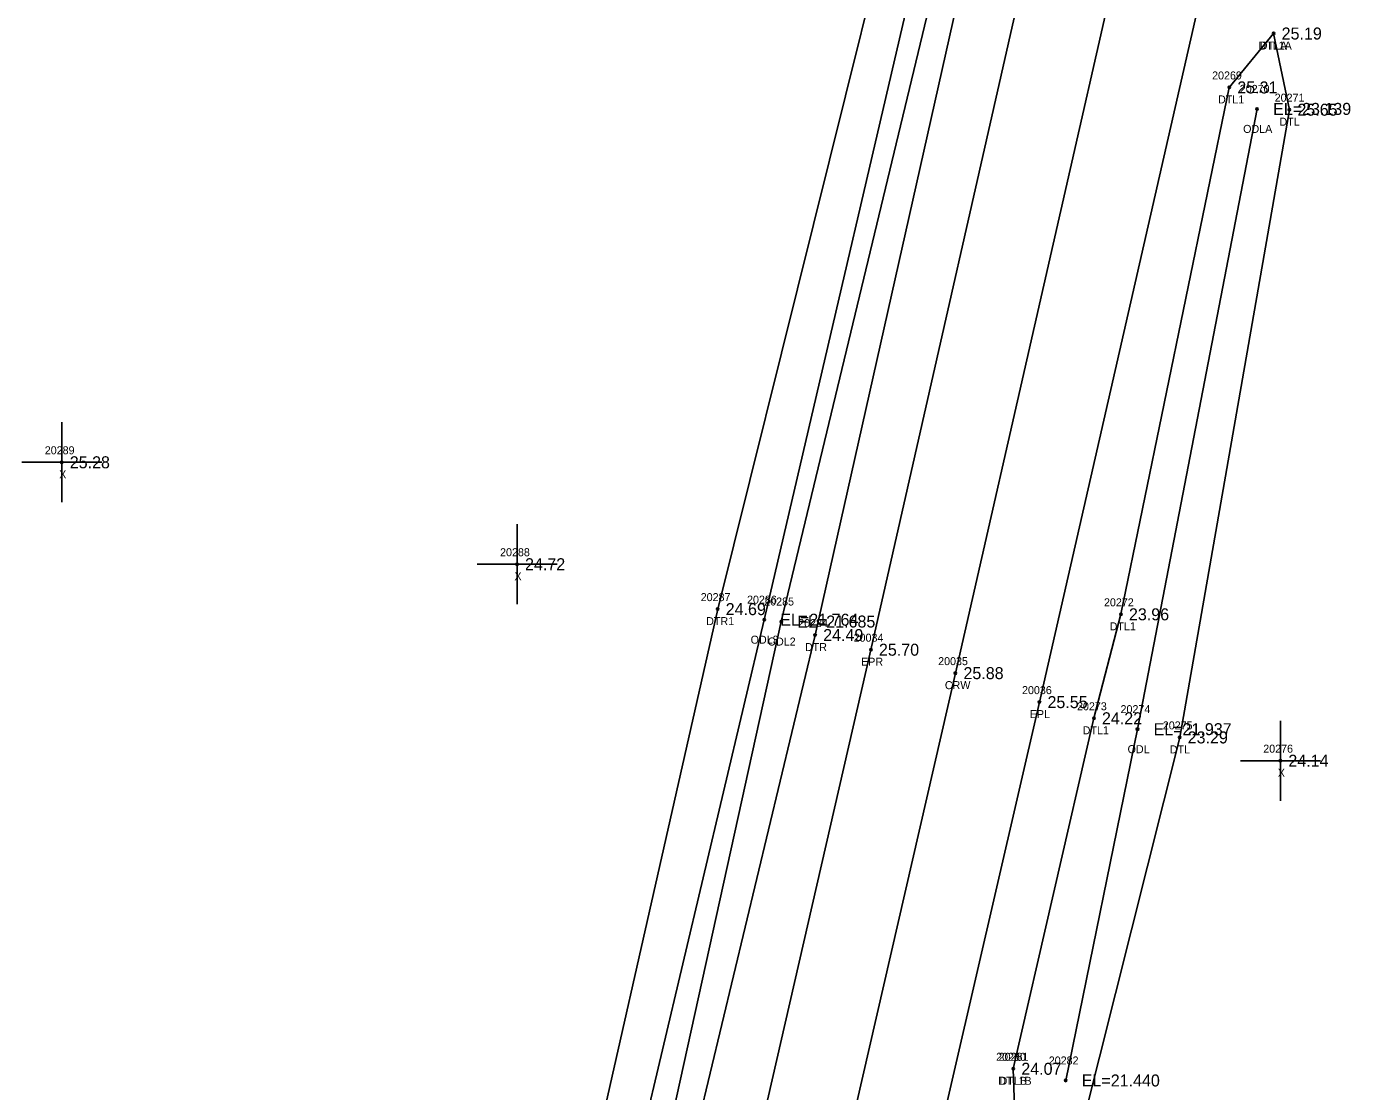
# Model space of a CAD drawing. Extents: x 2655177 to 2656219, y 761780 to 764748.
# Drawn here: x 2655847.5 to 2656013, y 764278.4 to 764411.4 of the extents above; entities that cross this region are included whole.
import ezdxf

# ---------------------------------------------------------------- set-up
doc = ezdxf.new("R2010")
doc.units = 0
for name, color, linetype in [('RD_DTM_BkLn1', 7, 'Continuous'), ('RD_EX_H2O', 7, 'Continuous'), ('RD_EX_H2O_txCode', 7, 'Continuous'), ('RD_EX_Misc', 7, 'Continuous'), ('RD_EX_Misc_txCode', 7, 'Continuous'), ('RD_EX_Road', 7, 'Continuous'), ('RD_EX_Road_txCode', 7, 'Continuous'), ('RD_EX_TX_H2O_ELEV', 7, 'Continuous'), ('RD_EX_TX_Misc_ELEV', 7, 'Continuous'), ('RD_EX_TX_Road_ELEV', 7, 'Continuous'), ('RD_HC_Survey_ELEV', 7, 'Continuous'), ('RD_HC_Survey_txCode', 7, 'Continuous'), ('RD_SMD_Locator', 7, 'Continuous')]:
    doc.layers.add(name, color=color, linetype=linetype)

msp = doc.modelspace()

# ---------------------------------------------------------------- linework, layer by layer
at = {"layer": 'RD_DTM_BkLn1'}
msp.add_lwpolyline([(2656052.36, 764720.46), (2656029.22, 764619.66), (2656007.41, 764523.97), (2655985.61, 764427.64), (2655963.53, 764330.64), (2655941.2, 764233.56), (2655920.06, 764141.06), (2655898.52, 764047.86), (2655877.71, 763954.88), (2655855.89, 763859.81), (2655834.07, 763763.97), (2655811.81, 763666.79), (2655790.48, 763573.22), (2655769.27, 763483.63), (2655747.64, 763389.32), (2655725.4, 763293.96), (2655721.51, 763275.9)], dxfattribs=at)
at = {"layer": 'RD_EX_H2O'}
for points in [[(2655985.99, 764532.58), (2655990.84, 764527.53), (2655967.74, 764432.27), (2655946, 764335.4), (2655922.66, 764238.07), (2655902.06, 764145.42), (2655879.59, 764053.25), (2655859.1, 763959.14), (2655841.15, 763874.16), (2655837.57, 763865.39), (2655829.11, 763865.29), (2655761.29, 763886.78)], [(2655985.99, 764532.58), (2655980.45, 764530.42), (2655978.53, 764524.06), (2655957.73, 764434.81), (2655933.82, 764338.64), (2655911.79, 764241.24), (2655890.59, 764146.77), (2655869.91, 764054.39), (2655847.97, 763961.11)], [(2655983.66, 764527.79), (2655962.07, 764433.73), (2655939.64, 764337.32), (2655916.77, 764240.59), (2655893.69, 764145.91), (2655873.09, 764053.84), (2655852.96, 763960.1)], [(2655986.13, 764527.03), (2655964.81, 764432.99), (2655941.76, 764337.09), (2655920.19, 764238.99), (2655899.24, 764145.84), (2655875.75, 764053.31), (2655856.78, 763959.16), (2655834.97, 763871.07)], [(2656003.29, 764410.57), (2656005.26, 764401.05), (2655991.55, 764322.61), (2655977.47, 764266.58), (2655971.19, 764268.14), (2655970.76, 764281.2)], [(2656003.29, 764410.57), (2655997.75, 764403.83), (2655984.21, 764337.99), (2655980.84, 764325), (2655970.76, 764281.2)], [(2656001.22, 764401.15), (2655986.28, 764323.64), (2655977.31, 764279.74)]]:
    msp.add_lwpolyline(points, dxfattribs=at)
at = {"layer": 'RD_EX_Misc'}
for p, q in [((2655851.86, 764351.99), (2655851.86, 764361.99)), ((2655846.86, 764356.99), (2655856.86, 764356.99)), ((2655908.75, 764339.25), (2655908.75, 764349.25)), ((2655903.75, 764344.25), (2655913.75, 764344.25)), ((2656004.13, 764314.7), (2656004.13, 764324.7)), ((2655999.13, 764319.7), (2656009.13, 764319.7))]:
    msp.add_line(p, q, dxfattribs=at)
at = {"layer": 'RD_EX_Road'}
for points in [[(2656041.72, 764723.31), (2656018.5, 764622.03), (2656002.75, 764552.49), (2655997.43, 764530.02), (2655974.74, 764429.64), (2655952.97, 764333.57), (2655930.52, 764235.7), (2655909.18, 764142.93), (2655887.93, 764050.57), (2655866.91, 763957.26), (2655846.82, 763869.53), (2655845.21, 763862.22), (2655839.99, 763839.71), (2655823.38, 763766.66), (2655801.33, 763669.93), (2655780.03, 763576.53), (2655774.26, 763551.85), (2655771.37, 763539.86), (2655759.09, 763486.9), (2655736.94, 763391.72), (2655715.19, 763296.77), (2655711.35, 763278.45)], [(2656062.87, 764717.57), (2656039.84, 764617.04), (2656035.41, 764597.94), (2656033.38, 764589.18), (2656018.27, 764522.6), (2656017.22, 764517.64), (2656011.07, 764490.22), (2655996.52, 764425.63), (2655974.03, 764327.02), (2655960.71, 764269.34), (2655951.96, 764231.59), (2655930.84, 764138.62), (2655926.81, 764121.01)]]:
    msp.add_lwpolyline(points, dxfattribs=at)
at = {"layer": 'RD_SMD_Locator'}
for centre in [(2656003.29, 764410.57), (2656003.29, 764410.57), (2655997.75, 764403.83), (2656001.22, 764401.15), (2656005.26, 764401.05), (2655851.86, 764356.99), (2655908.75, 764344.25), (2655933.82, 764338.64), (2655939.64, 764337.32), (2655984.21, 764337.99), (2655941.76, 764337.09), (2655946, 764335.4), (2655952.97, 764333.57), (2655963.53, 764330.64), (2655974.03, 764327.02), (2655980.84, 764325), (2655986.28, 764323.64), (2655991.55, 764322.61), (2656004.13, 764319.7), (2655970.76, 764281.2), (2655970.76, 764281.2), (2655977.31, 764279.74)]:
    msp.add_circle(centre, 0.15, dxfattribs=at)

# ---------------------------------------------------------------- texts
at = {"layer": 'RD_EX_H2O_txCode'}
for s, p in [('DTL1A', (2656001.39, 764408.57)), ('DTLA', (2656001.56, 764408.57)), ('20269', (2655995.6, 764404.83)), ('20270', (2655999.06, 764403.15)), ('DTL1', (2655996.34, 764401.83)), ('20271', (2656003.42, 764402.05)), ('ODLA', (2655999.48, 764398.15)), ('DTL', (2656004.01, 764399.05)), ('20287', (2655931.7, 764339.64)), ('20286', (2655937.49, 764339.32)), ('20285', (2655939.64, 764339.09)), ('20272', (2655982.09, 764338.99)), ('DTR1', (2655932.38, 764336.64)), ('20284', (2655943.88, 764336.4)), ('DTL1', (2655982.8, 764335.99)), ('ODL3', (2655937.94, 764334.32)), ('ODL2', (2655940.07, 764334.09)), ('DTR', (2655944.73, 764333.4)), ('20273', (2655978.72, 764326)), ('20274', (2655984.16, 764325.64)), ('20275', (2655989.44, 764323.61)), ('DTL1', (2655979.43, 764323)), ('ODL', (2655985.04, 764320.64)), ('DTL', (2655990.31, 764320.61)), ('20280', (2655968.61, 764282.2)), ('20281', (2655968.93, 764282.2)), ('20282', (2655975.19, 764281.74)), ('DTL1B', (2655968.88, 764279.2)), ('DTLB', (2655969.05, 764279.2))]:
    msp.add_text(s, height=1, dxfattribs=at).set_placement(p)
at = {"layer": 'RD_EX_Misc_txCode'}
for s, p in [('20289', (2655849.74, 764357.99)), ('X', (2655851.54, 764354.99)), ('20288', (2655906.63, 764345.25)), ('X', (2655908.43, 764342.25)), ('20276', (2656001.99, 764320.7)), ('X', (2656003.81, 764317.7))]:
    msp.add_text(s, height=1, dxfattribs=at).set_placement(p)
at = {"layer": 'RD_EX_Road_txCode'}
for s, p in [('20034', (2655950.81, 764334.57)), ('EPR', (2655951.74, 764331.57)), ('20036', (2655971.85, 764328.02)), ('EPL', (2655972.82, 764325.02))]:
    msp.add_text(s, height=1, dxfattribs=at).set_placement(p)
at = {"layer": 'RD_EX_TX_H2O_ELEV'}
for s, p in [('25.19', (2656004.29, 764409.82)), ('25.19', (2656004.29, 764409.82)), ('25.31', (2655998.75, 764403.08)), ('EL=23.139', (2656003.22, 764400.4)), ('25.65', (2656006.26, 764400.3)), ('24.69', (2655934.82, 764337.89)), ('EL=21.764', (2655941.64, 764336.57)), ('EL=21.685', (2655943.76, 764336.34)), ('23.96', (2655985.21, 764337.24)), ('24.49', (2655947, 764334.65)), ('24.22', (2655981.84, 764324.25)), ('EL=21.937', (2655988.28, 764322.89)), ('23.29', (2655992.55, 764321.86)), ('24.07', (2655971.76, 764280.45)), ('24.07', (2655971.76, 764280.45)), ('EL=21.440', (2655979.31, 764278.99))]:
    msp.add_text(s, height=1.5, dxfattribs=at).set_placement(p)
at = {"layer": 'RD_EX_TX_Misc_ELEV'}
for s, p in [('25.28', (2655852.86, 764356.24)), ('24.72', (2655909.75, 764343.5)), ('24.14', (2656005.13, 764318.95))]:
    msp.add_text(s, height=1.5, dxfattribs=at).set_placement(p)
at = {"layer": 'RD_EX_TX_Road_ELEV'}
for s, p in [('25.70', (2655953.97, 764332.82)), ('25.55', (2655975.03, 764326.27))]:
    msp.add_text(s, height=1.5, dxfattribs=at).set_placement(p)
at = {"layer": 'RD_HC_Survey_ELEV'}
msp.add_text('25.88', height=1.5, dxfattribs=at).set_placement((2655964.53, 764329.89))
at = {"layer": 'RD_HC_Survey_txCode'}
for s, p in [('20035', (2655961.37, 764331.64)), ('CRW', (2655962.21, 764328.64))]:
    msp.add_text(s, height=1, dxfattribs=at).set_placement(p)

doc.saveas('drawing.dxf')
